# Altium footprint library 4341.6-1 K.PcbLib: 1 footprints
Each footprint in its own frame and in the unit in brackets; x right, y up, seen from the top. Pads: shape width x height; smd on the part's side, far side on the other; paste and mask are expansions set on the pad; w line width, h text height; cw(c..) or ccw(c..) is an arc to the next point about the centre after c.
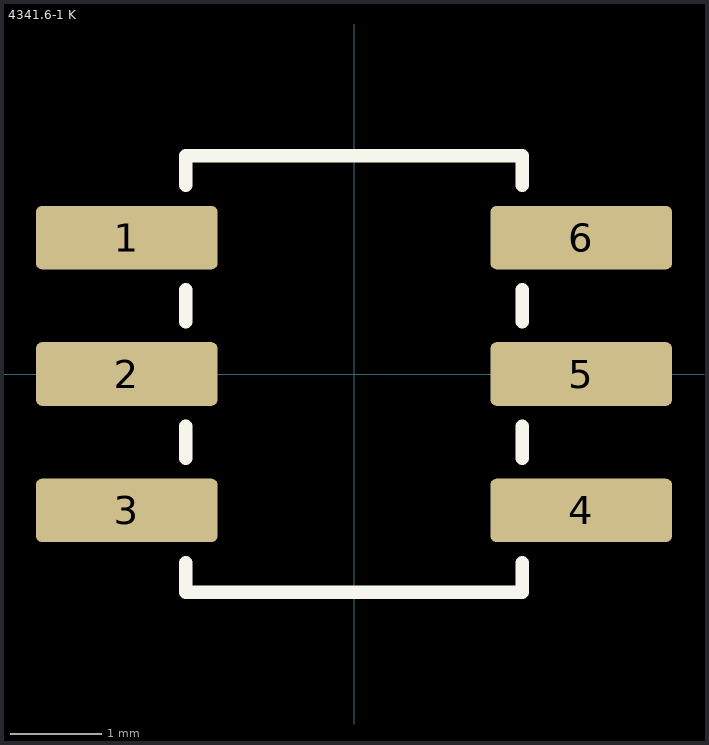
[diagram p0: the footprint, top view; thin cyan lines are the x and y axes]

## 4341.6-1 K [mm]
pads (6):
  rrect20% 2x0.7 smd mask+0: 1(-2.5,1.5) 2(-2.5,0) 3(-2.5,-1.5) 4(2.5,-1.5) 5(2.5,0) 6(2.5,1.5)
Top Overlay:
  lines w0.15: -1.85,-2.075 -1.85,-2.4 1.85,-2.4 1.85,-2.075 ; -1.85,-0.925 -1.85,-0.575 ; -1.85,0.575 -1.85,0.925 ; -1.85,2.075 -1.85,2.4 1.85,2.4 1.85,2.075 ; 1.85,-0.925 1.85,-0.575 ; 1.85,0.575 1.85,0.925
  text "." at -2.72,2.285 h5
3D body "4341.6-1_K_SOIC6_P1.5.step": height 1.7, standoff 0, extent -3.15,-2.3 3.15,2.3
